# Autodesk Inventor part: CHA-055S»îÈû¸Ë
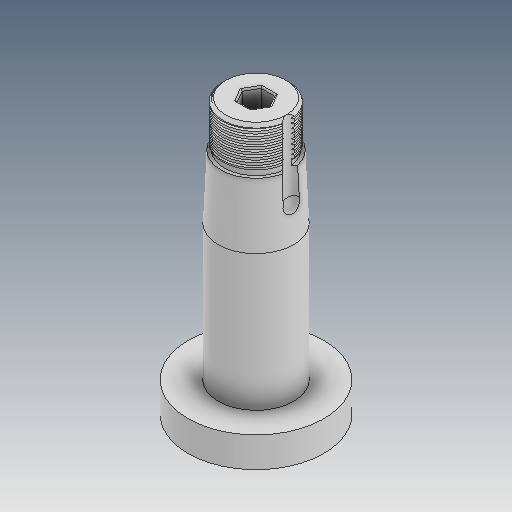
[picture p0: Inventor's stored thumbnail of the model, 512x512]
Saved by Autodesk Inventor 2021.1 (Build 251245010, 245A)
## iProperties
Created: 2019-12
Part Number: CHA-055S»îÈû¸Ë
Material: Ogólny
Document SubType Name: Modeling
Designer: user
Density: 1 g/cm^3
Appearance: Domyślna
Author: user
Revision Number: ÈÎºÎ
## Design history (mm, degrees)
feature "ÊäÈë1"
node "Bryła1"
